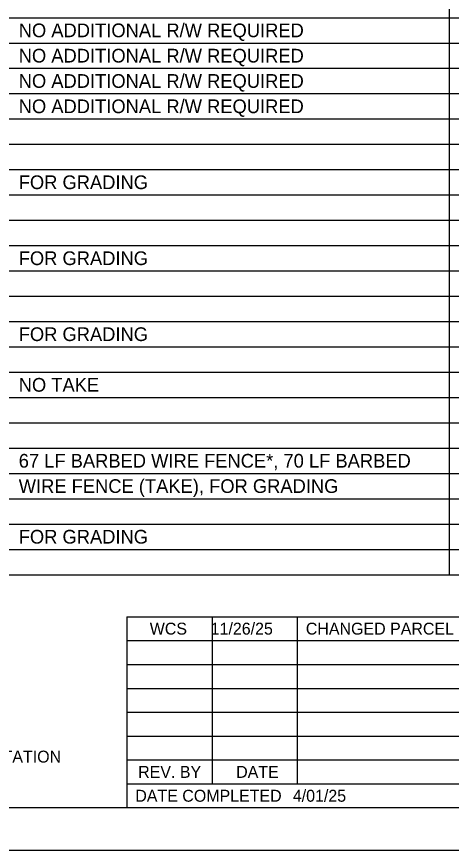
# Model space of a CAD drawing. Extents: x -1.7 to 34, y -55.6 to 22.
# Drawn here: x 23.91 to 29, y 0 to 9.78 of the extents above; entities that cross this region are included whole.
import ezdxf

# ---------------------------------------------------------------- set-up
doc = ezdxf.new("R2010")
doc.units = 0
for name, color, linetype in [('SH_Border', 7, 'Continuous'), ('SH_Cut_Line', 7, 'Continuous'), ('SH_Text', 7, 'Continuous')]:
    doc.layers.add(name, color=color, linetype=linetype)

msp = doc.modelspace()

# ---------------------------------------------------------------- linework, layer by layer
at = {"layer": 'SH_Border'}
msp.add_lwpolyline([(1.5, 21.5), (33.5, 21.5), (33.5, 0.5), (1.5, 0.5)], close=True, dxfattribs=at)
at = {"layer": 'SH_Cut_Line'}
msp.add_lwpolyline([(0, 0), (34, 0), (34, 22), (0, 22)], close=True, dxfattribs=at)
at = {"layer": 'SH_Text'}
for p, q in [((28.9779, 20.806), (28.9779, 3.2327)), ((1.5, 9.7659), (31.1091, 9.7659)), ((1.5, 9.4689), (31.1091, 9.4689)), ((1.5, 9.172), (31.1091, 9.172)), ((1.5, 8.875), (31.1091, 8.875)), ((1.5, 8.578), (31.1091, 8.578)), ((1.5, 8.2811), (31.1091, 8.2811)), ((1.5, 7.9841), (31.1091, 7.9841)), ((1.5, 7.6871), (31.1091, 7.6871)), ((1.5, 7.3902), (31.1091, 7.3902)), ((1.5, 7.0932), (31.1091, 7.0932)), ((1.5, 6.7962), (31.1091, 6.7962)), ((1.5, 6.4993), (31.1091, 6.4993)), ((1.5, 6.2023), (31.1091, 6.2023)), ((1.5, 5.9053), (31.1091, 5.9053)), ((1.5, 5.6084), (31.1091, 5.6084)), ((1.5, 5.3114), (31.1091, 5.3114)), ((1.5, 5.0145), (31.1091, 5.0145)), ((1.5, 4.7175), (31.1091, 4.7175)), ((1.5, 4.4205), (31.1091, 4.4205)), ((1.5, 4.1236), (31.1091, 4.1236)), ((1.5, 3.8266), (31.1091, 3.8266)), ((1.5, 3.5296), (31.1091, 3.5296)), ((1.5, 3.2327), (31.1091, 3.2327)), ((25.1966, 2.74), (25.1966, 0.5)), ((25.1966, 2.74), (32, 2.74)), ((26.1966, 2.74), (26.1966, 0.78)), ((27.1966, 2.74), (27.1966, 0.78)), ((25.1966, 2.46), (32, 2.46)), ((25.1966, 2.18), (32, 2.18)), ((25.1966, 1.9), (32, 1.9)), ((25.1966, 1.62), (32, 1.62)), ((25.1966, 1.34), (32, 1.34)), ((25.1966, 1.06), (32, 1.06)), ((25.1966, 0.78), (32, 0.78))]:
    msp.add_line(p, q, dxfattribs=at)

# ---------------------------------------------------------------- texts
for s, height, p in [('NO ADDITIONAL R/W REQUIRED', 0.16071, (23.9296, 9.537)), ('NO ADDITIONAL R/W REQUIRED', 0.16071, (23.9296, 9.2401)), ('NO ADDITIONAL R/W REQUIRED', 0.16071, (23.9296, 8.9431)), ('NO ADDITIONAL R/W REQUIRED', 0.16071, (23.9296, 8.6462)), ('FOR GRADING', 0.16071, (23.9296, 7.7553)), ('FOR GRADING', 0.16071, (23.9296, 6.8644)), ('FOR GRADING', 0.16071, (23.9296, 5.9735)), ('NO TAKE', 0.16071, (23.9296, 5.3795)), ('67 LF BARBED WIRE FENCE*, 70 LF BARBED', 0.16071, (23.9296, 4.4886)), ('WIRE FENCE (TAKE), FOR GRADING', 0.16071, (23.9296, 4.1917)), ('FOR GRADING', 0.16071, (23.9296, 3.5978)), ('WCS', 0.14, (25.4663, 2.53)), ('11/26/25', 0.14, (26.181, 2.53)), ('CHANGED PARCEL 9 OWNERS RECORD.', 0.14, (27.2966, 2.53)), ('THE STATE OF OHIO DEPARTMENT OF TRANSPORTATION', 0.14, (19.1224, 1.0292)), ('REV. BY', 0.14, (25.3304, 0.85)), ('DATE', 0.14, (26.4797, 0.85)), ('DATE COMPLETED', 0.14, (25.2966, 0.57)), ('4/01/25', 0.14, (27.1443, 0.57))]:
    msp.add_text(s, height=height, dxfattribs=at).set_placement(p)

doc.saveas('drawing.dxf')
